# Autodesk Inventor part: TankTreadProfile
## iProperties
Created: 2008-04
Part Number: TankTreadProfile
Document SubType Name: Modeling
Density: 1 g/cm^3
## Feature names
1. Extrusion1
2. Extrusion4
